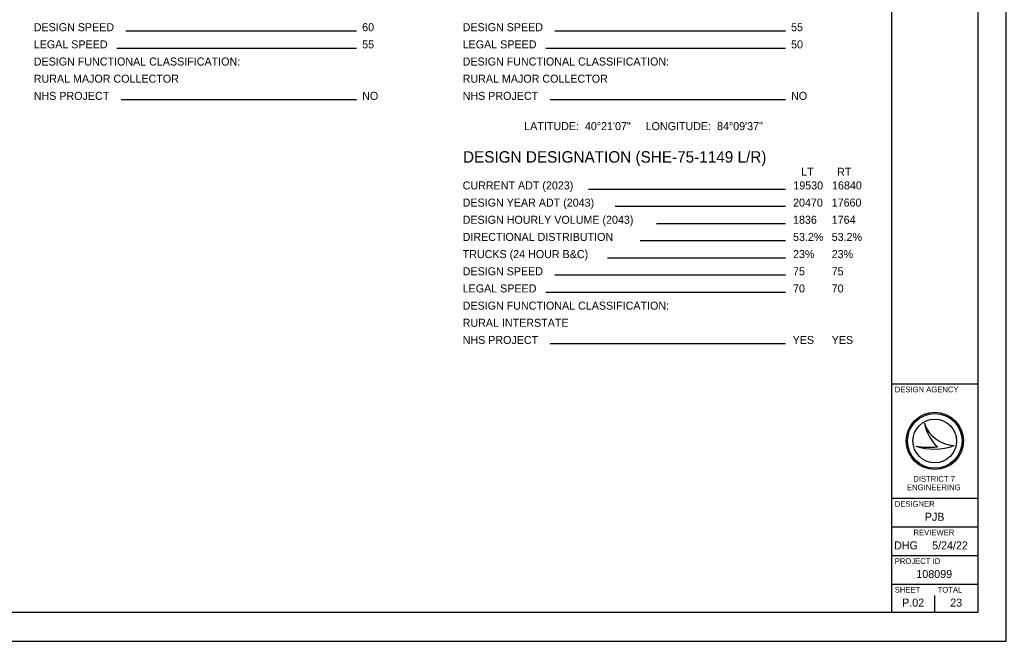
# Model space of a CAD drawing. Extents: x 0 to 1391, y -24 to 440.
# Drawn here: x 335 to 680, y 0 to 217.2 of the extents above; entities that cross this region are included whole.
import ezdxf

# ---------------------------------------------------------------- set-up
doc = ezdxf.new("R2010")
doc.units = 0
for name, color, linetype in [('SH_Border', 7, 'Continuous'), ('SH_Cut_Line', 7, 'Continuous'), ('SH_Data', 7, 'Continuous'), ('SH_Text', 7, 'Continuous')]:
    doc.layers.add(name, color=color, linetype=linetype)

msp = doc.modelspace()

# ---------------------------------------------------------------- linework, layer by layer
at = {"layer": 'SH_Border'}
for p, q in [((640, 10), (640, 430)), ((640, 90), (670, 90)), ((640, 50), (670, 50)), ((640, 40), (670, 40)), ((640, 30), (670, 30)), ((640, 20), (670, 20))]:
    msp.add_line(p, q, dxfattribs=at)
msp.add_lwpolyline([(30, 430), (670, 430), (670, 10), (30, 10)], close=True, dxfattribs=at)
at = {"layer": 'SH_Cut_Line'}
msp.add_lwpolyline([(0, 0), (680, 0), (680, 440), (0, 440)], close=True, dxfattribs=at)
at = {"layer": 'SH_Data'}
for p, q in [((452.74, 213.19), (372.07, 213.19)), ((602.74, 213.19), (522.07, 213.19)), ((452.74, 207.19), (368.98, 207.19)), ((602.74, 207.19), (518.98, 207.19)), ((452.74, 189.19), (370.49, 189.19)), ((602.74, 189.19), (520.49, 189.19)), ((602.85, 157.89), (533.87, 157.89)), ((602.74, 151.89), (543.18, 151.89)), ((602.74, 145.89), (557.7, 145.89)), ((602.74, 139.89), (551.98, 139.89)), ((602.74, 133.89), (540.52, 133.89)), ((602.74, 127.89), (522.07, 127.89)), ((602.74, 121.89), (518.98, 121.89)), ((602.74, 103.89), (520.49, 103.89)), ((651.35, 76.19), (651.35, 76.19)), ((655, 70), (655, 70)), ((648.34, 68.19), (648.34, 68.19)), ((661.75, 68.37), (661.75, 68.37)), ((655, 10), (655, 16)), ((647.5, 13.5), (647.5, 13.5))]:
    msp.add_line(p, q, dxfattribs=at)
for radius in [10, 9.54, 9.54, 7.64]:
    msp.add_circle((655, 70), radius, dxfattribs=at)
for centre, radius, start, end in [((662.32, 79.95), 11.6, 198.9257, 198.9319), ((666.93, 79.4), 15.91, 191.6379, 191.6421), ((662.32, 79.95), 11.6, 198.9319, 267.1657), ((666.93, 79.4), 15.91, 191.6421, 226.0947), ((654.79, 87.4), 20.26, 251.4576, 290.0832), ((652.96, 93.09), 25.32, 259.4964, 259.4995), ((654.79, 87.4), 20.26, 251.4527, 251.4576), ((652.96, 93.09), 25.32, 259.4995, 276.6672)]:
    msp.add_arc(centre, radius, start, end, dxfattribs=at)

# ---------------------------------------------------------------- texts
for s, height, p in [('DESIGN DESIGNATION (SHE-75-1149 L/R)', 4, (490, 167.26)), ('DESIGN AGENCY', 2, (641, 87)), ('DESIGNER', 2, (641, 47)), ('PJB', 2.8, (651.52, 42.1)), ('REVIEWER', 2, (647.57, 37)), ('DHG', 2.8, (640.78, 32.1)), ('5/24/22', 2.8, (654.08, 32.1)), ('PROJECT ID', 2, (641, 27)), ('108099', 2.8, (648.56, 22.1)), ('SHEET', 2, (641, 17)), ('TOTAL', 2, (656, 17)), ('P.02', 2.8, (643.58, 12.1)), ('23', 2.8, (660.41, 12.1))]:
    msp.add_text(s, height=height, dxfattribs=at).set_placement(p)
at = {"layer": 'SH_Text'}
for s, height, p in [('DESIGN SPEED', 2.8, (339.89, 213.19)), ('60', 2.8, (454.74, 213.19)), ('DESIGN SPEED', 2.8, (489.89, 213.19)), ('55', 2.8, (604.74, 213.19)), ('LEGAL SPEED', 2.8, (339.89, 207.19)), ('55', 2.8, (454.74, 207.19)), ('LEGAL SPEED', 2.8, (489.89, 207.19)), ('50', 2.8, (604.74, 207.19)), ('DESIGN FUNCTIONAL CLASSIFICATION:', 2.8, (339.89, 201.19)), ('DESIGN FUNCTIONAL CLASSIFICATION:', 2.8, (489.89, 201.19)), ('RURAL MAJOR COLLECTOR', 2.8, (339.89, 195.19)), ('RURAL MAJOR COLLECTOR', 2.8, (489.89, 195.19)), ('NHS PROJECT', 2.8, (339.89, 189.19)), ('NO', 2.8, (454.74, 189.19)), ('NHS PROJECT', 2.8, (489.89, 189.19)), ('NO', 2.8, (604.74, 189.19)), ('LATITUDE:  40°21\'07"     LONGITUDE:  84°09\'37"', 2.8, (511.42, 178.61)), ('LT', 2.8, (608.28, 162.7)), ('RT', 2.8, (620.83, 162.65)), ('CURRENT ADT (2023)', 2.8, (489.89, 157.89)), ('19530', 2.8, (605.54, 157.89)), ('16840', 2.8, (619.07, 157.89)), ('DESIGN YEAR ADT (2043)', 2.8, (489.89, 151.89)), ('20470', 2.8, (605.43, 151.89)), ('17660', 2.8, (618.95, 151.89)), ('DESIGN HOURLY VOLUME (2043)', 2.8, (489.89, 145.89)), ('1836', 2.8, (605.43, 145.89)), ('1764', 2.8, (618.95, 145.89)), ('DIRECTIONAL DISTRIBUTION', 2.8, (489.89, 139.89)), ('53.2%', 2.8, (605.43, 139.89)), ('53.2%', 2.8, (618.95, 139.89)), ('TRUCKS (24 HOUR B&C)', 2.8, (489.89, 133.89)), ('23%', 2.8, (605.43, 133.89)), ('23%', 2.8, (618.95, 133.89)), ('DESIGN SPEED', 2.8, (489.89, 127.89)), ('75', 2.8, (605.43, 127.89)), ('75', 2.8, (618.95, 127.89)), ('LEGAL SPEED', 2.8, (489.89, 121.89)), ('70', 2.8, (605.43, 121.89)), ('70', 2.8, (618.95, 121.89)), ('DESIGN FUNCTIONAL CLASSIFICATION:', 2.8, (489.89, 115.89)), ('RURAL INTERSTATE', 2.8, (489.89, 109.89)), ('NHS PROJECT', 2.8, (489.89, 103.89)), ('YES', 2.8, (605.29, 103.89)), ('YES', 2.8, (618.95, 103.89)), ('DISTRICT 7', 2, (647.48, 55.77)), ('ENGINEERING', 2, (645.3, 52.77))]:
    msp.add_text(s, height=height, dxfattribs=at).set_placement(p)

doc.saveas('drawing.dxf')
